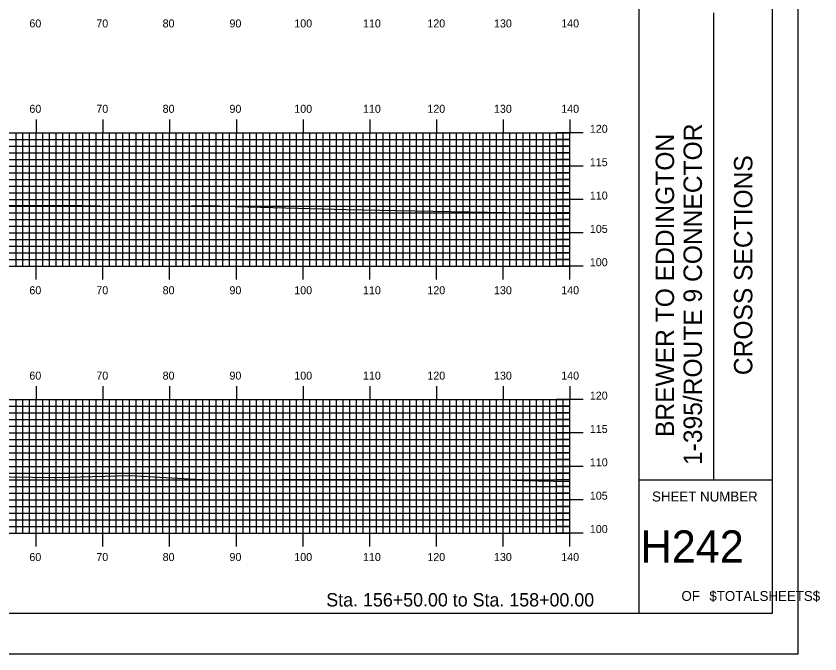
# Model space of a CAD drawing. Extents: x 1779499 to 1779842, y 442591 to 442811.
# Drawn here: x 1779721.8 to 1779842.3, y 442590.5 to 442686.2 of the extents above; entities that cross this region are included whole.
import ezdxf

# ---------------------------------------------------------------- set-up
doc = ezdxf.new("R2010")
doc.units = 0
for name, color, linetype in [('BORDER', 7, 'Continuous'), ('H_V ANNOTATION', 7, 'Continuous'), ('MAJOR', 7, 'Continuous'), ('MINOR', 7, 'Continuous'), ('PLOT BOUNDARY', 7, 'Continuous'), ('S_Roadway_Centerline', 7, 'Continuous')]:
    doc.layers.add(name, color=color, linetype=linetype)

msp = doc.modelspace()

# ---------------------------------------------------------------- linework, layer by layer
at = {"layer": 'BORDER'}
for p, q in [((1779815.24, 442596.67), (1779815.24, 442806.67)), ((1779826.42, 442616.67), (1779826.42, 442686.67)), ((1779815.24, 442616.67), (1779835.24, 442616.67))]:
    msp.add_line(p, q, dxfattribs=at)
msp.add_lwpolyline([(1779515.24, 442596.67), (1779835.24, 442596.67), (1779835.24, 442806.67), (1779515.24, 442806.67)], close=True, dxfattribs=at)
at = {"layer": 'MAJOR'}
for p, q in [((1779724.84, 442670.67), (1779724.84, 442668.67)), ((1779734.84, 442670.67), (1779734.84, 442668.67)), ((1779744.84, 442670.67), (1779744.84, 442668.67)), ((1779754.84, 442670.67), (1779754.84, 442668.67)), ((1779764.84, 442670.67), (1779764.84, 442668.67)), ((1779774.84, 442670.67), (1779774.84, 442668.67)), ((1779784.84, 442670.67), (1779784.84, 442668.67)), ((1779794.84, 442670.67), (1779794.84, 442668.67)), ((1779804.84, 442670.67), (1779804.84, 442668.67)), ((1779524.84, 442668.67), (1779804.84, 442668.67)), ((1779524.84, 442668.67), (1779804.84, 442668.67)), ((1779724.84, 442648.67), (1779724.84, 442668.67)), ((1779734.84, 442648.67), (1779734.84, 442668.67)), ((1779744.84, 442648.67), (1779744.84, 442668.67)), ((1779754.84, 442648.67), (1779754.84, 442668.67)), ((1779764.84, 442648.67), (1779764.84, 442668.67)), ((1779774.84, 442648.67), (1779774.84, 442668.67)), ((1779784.84, 442648.67), (1779784.84, 442668.67)), ((1779794.84, 442648.67), (1779794.84, 442668.67)), ((1779806.85, 442668.67), (1779802.84, 442668.67)), ((1779804.84, 442648.67), (1779804.84, 442668.67)), ((1779804.84, 442648.67), (1779804.84, 442668.67)), ((1779524.84, 442663.67), (1779804.84, 442663.67)), ((1779806.85, 442663.67), (1779802.84, 442663.67)), ((1779524.84, 442658.67), (1779804.84, 442658.67)), ((1779806.85, 442658.67), (1779802.84, 442658.67)), ((1779524.84, 442653.67), (1779804.84, 442653.67)), ((1779806.85, 442653.67), (1779802.84, 442653.67)), ((1779524.84, 442648.67), (1779804.84, 442648.67)), ((1779524.84, 442648.67), (1779804.84, 442648.67)), ((1779724.84, 442646.66), (1779724.84, 442648.67)), ((1779734.84, 442646.66), (1779734.84, 442648.67)), ((1779744.84, 442646.66), (1779744.84, 442648.67)), ((1779754.84, 442646.66), (1779754.84, 442648.67)), ((1779764.84, 442646.66), (1779764.84, 442648.67)), ((1779774.84, 442646.66), (1779774.84, 442648.67)), ((1779784.84, 442646.66), (1779784.84, 442648.67)), ((1779794.84, 442646.66), (1779794.84, 442648.67)), ((1779806.85, 442648.67), (1779802.84, 442648.67)), ((1779804.84, 442646.66), (1779804.84, 442648.67)), ((1779724.84, 442630.67), (1779724.84, 442628.67)), ((1779734.84, 442630.67), (1779734.84, 442628.67)), ((1779744.84, 442630.67), (1779744.84, 442628.67)), ((1779754.84, 442630.67), (1779754.84, 442628.67)), ((1779764.84, 442630.67), (1779764.84, 442628.67)), ((1779774.84, 442630.67), (1779774.84, 442628.67)), ((1779784.84, 442630.67), (1779784.84, 442628.67)), ((1779794.84, 442630.67), (1779794.84, 442628.67)), ((1779804.84, 442630.67), (1779804.84, 442628.67)), ((1779524.84, 442628.67), (1779804.84, 442628.67)), ((1779524.84, 442628.67), (1779804.84, 442628.67)), ((1779724.84, 442608.67), (1779724.84, 442628.67)), ((1779734.84, 442608.67), (1779734.84, 442628.67)), ((1779744.84, 442608.67), (1779744.84, 442628.67)), ((1779754.84, 442608.67), (1779754.84, 442628.67)), ((1779764.84, 442608.67), (1779764.84, 442628.67)), ((1779774.84, 442608.67), (1779774.84, 442628.67)), ((1779784.84, 442608.67), (1779784.84, 442628.67)), ((1779794.84, 442608.67), (1779794.84, 442628.67)), ((1779806.85, 442628.67), (1779802.84, 442628.67)), ((1779804.84, 442608.67), (1779804.84, 442628.67)), ((1779804.84, 442608.67), (1779804.84, 442628.67)), ((1779524.84, 442623.67), (1779804.84, 442623.67)), ((1779806.85, 442623.67), (1779802.84, 442623.67)), ((1779524.84, 442618.67), (1779804.84, 442618.67)), ((1779806.85, 442618.67), (1779802.84, 442618.67)), ((1779524.84, 442613.67), (1779804.84, 442613.67)), ((1779806.85, 442613.67), (1779802.84, 442613.67)), ((1779524.84, 442608.67), (1779804.84, 442608.67)), ((1779524.84, 442608.67), (1779804.84, 442608.67)), ((1779724.84, 442606.66), (1779724.84, 442608.67)), ((1779734.84, 442606.66), (1779734.84, 442608.67)), ((1779744.84, 442606.66), (1779744.84, 442608.67)), ((1779754.84, 442606.66), (1779754.84, 442608.67)), ((1779764.84, 442606.66), (1779764.84, 442608.67)), ((1779774.84, 442606.66), (1779774.84, 442608.67)), ((1779784.84, 442606.66), (1779784.84, 442608.67)), ((1779794.84, 442606.66), (1779794.84, 442608.67)), ((1779806.85, 442608.67), (1779802.84, 442608.67)), ((1779804.84, 442606.66), (1779804.84, 442608.67))]:
    msp.add_line(p, q, dxfattribs=at)
at = {"layer": 'MINOR'}
for p, q in [((1779721.84, 442648.67), (1779721.84, 442668.67)), ((1779722.84, 442648.67), (1779722.84, 442668.67)), ((1779723.84, 442648.67), (1779723.84, 442668.67)), ((1779725.84, 442648.67), (1779725.84, 442668.67)), ((1779726.84, 442648.67), (1779726.84, 442668.67)), ((1779727.84, 442648.67), (1779727.84, 442668.67)), ((1779728.84, 442648.67), (1779728.84, 442668.67)), ((1779729.84, 442648.67), (1779729.84, 442668.67)), ((1779730.84, 442648.67), (1779730.84, 442668.67)), ((1779731.84, 442648.67), (1779731.84, 442668.67)), ((1779732.84, 442648.67), (1779732.84, 442668.67)), ((1779733.84, 442648.67), (1779733.84, 442668.67)), ((1779735.84, 442648.67), (1779735.84, 442668.67)), ((1779736.84, 442648.67), (1779736.84, 442668.67)), ((1779737.84, 442648.67), (1779737.84, 442668.67)), ((1779738.84, 442648.67), (1779738.84, 442668.67)), ((1779739.84, 442648.67), (1779739.84, 442668.67)), ((1779740.84, 442648.67), (1779740.84, 442668.67)), ((1779741.84, 442648.67), (1779741.84, 442668.67)), ((1779742.84, 442648.67), (1779742.84, 442668.67)), ((1779743.84, 442648.67), (1779743.84, 442668.67)), ((1779745.84, 442648.67), (1779745.84, 442668.67)), ((1779746.84, 442648.67), (1779746.84, 442668.67)), ((1779747.84, 442648.67), (1779747.84, 442668.67)), ((1779748.84, 442648.67), (1779748.84, 442668.67)), ((1779749.84, 442648.67), (1779749.84, 442668.67)), ((1779750.84, 442648.67), (1779750.84, 442668.67)), ((1779751.84, 442648.67), (1779751.84, 442668.67)), ((1779752.84, 442648.67), (1779752.84, 442668.67)), ((1779753.84, 442648.67), (1779753.84, 442668.67)), ((1779755.84, 442648.67), (1779755.84, 442668.67)), ((1779756.84, 442648.67), (1779756.84, 442668.67)), ((1779757.84, 442648.67), (1779757.84, 442668.67)), ((1779758.84, 442648.67), (1779758.84, 442668.67)), ((1779759.84, 442648.67), (1779759.84, 442668.67)), ((1779760.84, 442648.67), (1779760.84, 442668.67)), ((1779761.84, 442648.67), (1779761.84, 442668.67)), ((1779762.84, 442648.67), (1779762.84, 442668.67)), ((1779763.84, 442648.67), (1779763.84, 442668.67)), ((1779765.84, 442648.67), (1779765.84, 442668.67)), ((1779766.84, 442648.67), (1779766.84, 442668.67)), ((1779767.84, 442648.67), (1779767.84, 442668.67)), ((1779768.84, 442648.67), (1779768.84, 442668.67)), ((1779769.84, 442648.67), (1779769.84, 442668.67)), ((1779770.84, 442648.67), (1779770.84, 442668.67)), ((1779771.84, 442648.67), (1779771.84, 442668.67)), ((1779772.84, 442648.67), (1779772.84, 442668.67)), ((1779773.84, 442648.67), (1779773.84, 442668.67)), ((1779775.84, 442648.67), (1779775.84, 442668.67)), ((1779776.84, 442648.67), (1779776.84, 442668.67)), ((1779777.84, 442648.67), (1779777.84, 442668.67)), ((1779778.84, 442648.67), (1779778.84, 442668.67)), ((1779779.84, 442648.67), (1779779.84, 442668.67)), ((1779780.84, 442648.67), (1779780.84, 442668.67)), ((1779781.84, 442648.67), (1779781.84, 442668.67)), ((1779782.84, 442648.67), (1779782.84, 442668.67)), ((1779783.84, 442648.67), (1779783.84, 442668.67)), ((1779785.84, 442648.67), (1779785.84, 442668.67)), ((1779786.84, 442648.67), (1779786.84, 442668.67)), ((1779787.84, 442648.67), (1779787.84, 442668.67)), ((1779788.84, 442648.67), (1779788.84, 442668.67)), ((1779789.84, 442648.67), (1779789.84, 442668.67)), ((1779790.84, 442648.67), (1779790.84, 442668.67)), ((1779791.84, 442648.67), (1779791.84, 442668.67)), ((1779792.84, 442648.67), (1779792.84, 442668.67)), ((1779793.84, 442648.67), (1779793.84, 442668.67)), ((1779795.84, 442648.67), (1779795.84, 442668.67)), ((1779796.84, 442648.67), (1779796.84, 442668.67)), ((1779797.84, 442648.67), (1779797.84, 442668.67)), ((1779798.84, 442648.67), (1779798.84, 442668.67)), ((1779799.84, 442648.67), (1779799.84, 442668.67)), ((1779800.84, 442648.67), (1779800.84, 442668.67)), ((1779801.84, 442648.67), (1779801.84, 442668.67)), ((1779802.84, 442648.67), (1779802.84, 442668.67)), ((1779803.84, 442648.67), (1779803.84, 442668.67)), ((1779524.84, 442667.67), (1779804.84, 442667.67)), ((1779804.84, 442667.67), (1779802.84, 442667.67)), ((1779524.84, 442666.67), (1779804.84, 442666.67)), ((1779804.84, 442666.67), (1779802.84, 442666.67)), ((1779524.84, 442665.67), (1779804.84, 442665.67)), ((1779804.84, 442665.67), (1779802.84, 442665.67)), ((1779524.84, 442664.67), (1779804.84, 442664.67)), ((1779804.84, 442664.67), (1779802.84, 442664.67)), ((1779524.84, 442662.67), (1779804.84, 442662.67)), ((1779804.84, 442662.67), (1779802.84, 442662.67)), ((1779524.84, 442661.67), (1779804.84, 442661.67)), ((1779804.84, 442661.67), (1779802.84, 442661.67)), ((1779524.84, 442660.67), (1779804.84, 442660.67)), ((1779804.84, 442660.67), (1779802.84, 442660.67)), ((1779524.84, 442659.67), (1779804.84, 442659.67)), ((1779804.84, 442659.67), (1779802.84, 442659.67)), ((1779524.84, 442657.67), (1779804.84, 442657.67)), ((1779804.84, 442657.67), (1779802.84, 442657.67)), ((1779524.84, 442656.67), (1779804.84, 442656.67)), ((1779804.84, 442656.67), (1779802.84, 442656.67)), ((1779524.84, 442655.67), (1779804.84, 442655.67)), ((1779804.84, 442655.67), (1779802.84, 442655.67)), ((1779524.84, 442654.67), (1779804.84, 442654.67)), ((1779804.84, 442654.67), (1779802.84, 442654.67)), ((1779524.84, 442652.67), (1779804.84, 442652.67)), ((1779524.84, 442651.67), (1779804.84, 442651.67)), ((1779804.84, 442652.67), (1779802.84, 442652.67)), ((1779804.84, 442651.67), (1779802.84, 442651.67)), ((1779524.84, 442650.67), (1779804.84, 442650.67)), ((1779804.84, 442650.67), (1779802.84, 442650.67)), ((1779524.84, 442649.67), (1779804.84, 442649.67)), ((1779804.84, 442649.67), (1779802.84, 442649.67)), ((1779721.84, 442608.67), (1779721.84, 442628.67)), ((1779722.84, 442608.67), (1779722.84, 442628.67)), ((1779723.84, 442608.67), (1779723.84, 442628.67)), ((1779725.84, 442608.67), (1779725.84, 442628.67)), ((1779726.84, 442608.67), (1779726.84, 442628.67)), ((1779727.84, 442608.67), (1779727.84, 442628.67)), ((1779728.84, 442608.67), (1779728.84, 442628.67)), ((1779729.84, 442608.67), (1779729.84, 442628.67)), ((1779730.84, 442608.67), (1779730.84, 442628.67)), ((1779731.84, 442608.67), (1779731.84, 442628.67)), ((1779732.84, 442608.67), (1779732.84, 442628.67)), ((1779733.84, 442608.67), (1779733.84, 442628.67)), ((1779735.84, 442608.67), (1779735.84, 442628.67)), ((1779736.84, 442608.67), (1779736.84, 442628.67)), ((1779737.84, 442608.67), (1779737.84, 442628.67)), ((1779738.84, 442608.67), (1779738.84, 442628.67)), ((1779739.84, 442608.67), (1779739.84, 442628.67)), ((1779740.84, 442608.67), (1779740.84, 442628.67)), ((1779741.84, 442608.67), (1779741.84, 442628.67)), ((1779742.84, 442608.67), (1779742.84, 442628.67)), ((1779743.84, 442608.67), (1779743.84, 442628.67)), ((1779745.84, 442608.67), (1779745.84, 442628.67)), ((1779746.84, 442608.67), (1779746.84, 442628.67)), ((1779747.84, 442608.67), (1779747.84, 442628.67)), ((1779748.84, 442608.67), (1779748.84, 442628.67)), ((1779749.84, 442608.67), (1779749.84, 442628.67)), ((1779750.84, 442608.67), (1779750.84, 442628.67)), ((1779751.84, 442608.67), (1779751.84, 442628.67)), ((1779752.84, 442608.67), (1779752.84, 442628.67)), ((1779753.84, 442608.67), (1779753.84, 442628.67)), ((1779755.84, 442608.67), (1779755.84, 442628.67)), ((1779756.84, 442608.67), (1779756.84, 442628.67)), ((1779757.84, 442608.67), (1779757.84, 442628.67)), ((1779758.84, 442608.67), (1779758.84, 442628.67)), ((1779759.84, 442608.67), (1779759.84, 442628.67)), ((1779760.84, 442608.67), (1779760.84, 442628.67)), ((1779761.84, 442608.67), (1779761.84, 442628.67)), ((1779762.84, 442608.67), (1779762.84, 442628.67)), ((1779763.84, 442608.67), (1779763.84, 442628.67)), ((1779765.84, 442608.67), (1779765.84, 442628.67)), ((1779766.84, 442608.67), (1779766.84, 442628.67)), ((1779767.84, 442608.67), (1779767.84, 442628.67)), ((1779768.84, 442608.67), (1779768.84, 442628.67)), ((1779769.84, 442608.67), (1779769.84, 442628.67)), ((1779770.84, 442608.67), (1779770.84, 442628.67)), ((1779771.84, 442608.67), (1779771.84, 442628.67)), ((1779772.84, 442608.67), (1779772.84, 442628.67)), ((1779773.84, 442608.67), (1779773.84, 442628.67)), ((1779775.84, 442608.67), (1779775.84, 442628.67)), ((1779776.84, 442608.67), (1779776.84, 442628.67)), ((1779777.84, 442608.67), (1779777.84, 442628.67)), ((1779778.84, 442608.67), (1779778.84, 442628.67)), ((1779779.84, 442608.67), (1779779.84, 442628.67)), ((1779780.84, 442608.67), (1779780.84, 442628.67)), ((1779781.84, 442608.67), (1779781.84, 442628.67)), ((1779782.84, 442608.67), (1779782.84, 442628.67)), ((1779783.84, 442608.67), (1779783.84, 442628.67)), ((1779785.84, 442608.67), (1779785.84, 442628.67)), ((1779786.84, 442608.67), (1779786.84, 442628.67)), ((1779787.84, 442608.67), (1779787.84, 442628.67)), ((1779788.84, 442608.67), (1779788.84, 442628.67)), ((1779789.84, 442608.67), (1779789.84, 442628.67)), ((1779790.84, 442608.67), (1779790.84, 442628.67)), ((1779791.84, 442608.67), (1779791.84, 442628.67)), ((1779792.84, 442608.67), (1779792.84, 442628.67)), ((1779793.84, 442608.67), (1779793.84, 442628.67)), ((1779795.84, 442608.67), (1779795.84, 442628.67)), ((1779796.84, 442608.67), (1779796.84, 442628.67)), ((1779797.84, 442608.67), (1779797.84, 442628.67)), ((1779798.84, 442608.67), (1779798.84, 442628.67)), ((1779799.84, 442608.67), (1779799.84, 442628.67)), ((1779800.84, 442608.67), (1779800.84, 442628.67)), ((1779801.84, 442608.67), (1779801.84, 442628.67)), ((1779802.84, 442608.67), (1779802.84, 442628.67)), ((1779803.84, 442608.67), (1779803.84, 442628.67)), ((1779524.84, 442627.67), (1779804.84, 442627.67)), ((1779804.84, 442627.67), (1779802.84, 442627.67)), ((1779524.84, 442626.67), (1779804.84, 442626.67)), ((1779804.84, 442626.67), (1779802.84, 442626.67)), ((1779524.84, 442625.67), (1779804.84, 442625.67)), ((1779804.84, 442625.67), (1779802.84, 442625.67)), ((1779524.84, 442624.67), (1779804.84, 442624.67)), ((1779804.84, 442624.67), (1779802.84, 442624.67)), ((1779524.84, 442622.67), (1779804.84, 442622.67)), ((1779804.84, 442622.67), (1779802.84, 442622.67)), ((1779524.84, 442621.67), (1779804.84, 442621.67)), ((1779804.84, 442621.67), (1779802.84, 442621.67)), ((1779524.84, 442620.67), (1779804.84, 442620.67)), ((1779804.84, 442620.67), (1779802.84, 442620.67)), ((1779524.84, 442619.67), (1779804.84, 442619.67)), ((1779804.84, 442619.67), (1779802.84, 442619.67)), ((1779524.84, 442617.67), (1779804.84, 442617.67)), ((1779524.84, 442616.67), (1779804.84, 442616.67)), ((1779804.84, 442617.67), (1779802.84, 442617.67)), ((1779804.84, 442616.67), (1779802.84, 442616.67)), ((1779524.84, 442615.67), (1779804.84, 442615.67)), ((1779804.84, 442615.67), (1779802.84, 442615.67)), ((1779524.84, 442614.67), (1779804.84, 442614.67)), ((1779804.84, 442614.67), (1779802.84, 442614.67)), ((1779524.84, 442612.67), (1779804.84, 442612.67)), ((1779804.84, 442612.67), (1779802.84, 442612.67)), ((1779524.84, 442611.67), (1779804.84, 442611.67)), ((1779524.84, 442610.67), (1779804.84, 442610.67)), ((1779804.84, 442611.67), (1779802.84, 442611.67)), ((1779804.84, 442610.67), (1779802.84, 442610.67)), ((1779524.84, 442609.67), (1779804.84, 442609.67)), ((1779804.84, 442609.67), (1779802.84, 442609.67))]:
    msp.add_line(p, q, dxfattribs=at)
at = {"layer": 'PLOT BOUNDARY'}
msp.add_lwpolyline([(1779499.06, 442590.55), (1779839.06, 442590.55), (1779839.06, 442810.55), (1779499.06, 442810.55)], close=True, dxfattribs=at)
at = {"layer": 'S_Roadway_Centerline'}
for points in [[(1779707.72, 442657.91), (1779724.69, 442657.78), (1779729.32, 442657.82), (1779739.44, 442657.64), (1779748.1, 442657.72), (1779751.05, 442657.76), (1779754.66, 442657.64), (1779764.11, 442657.36), (1779771.31, 442657.18), (1779778.89, 442657), (1779795.27, 442656.71), (1779798.16, 442656.62), (1779801.63, 442656.64), (1779804.84, 442656.61)], [(1779717.48, 442617.16), (1779727.58, 442616.98), (1779727.73, 442616.98), (1779727.81, 442616.98), (1779738.84, 442617.28), (1779749.74, 442616.7), (1779751.16, 442616.64), (1779761.66, 442616.72), (1779772.68, 442616.73), (1779772.86, 442616.73), (1779773.02, 442616.73), (1779777.13, 442616.71), (1779796.28, 442616.59), (1779797.03, 442616.59), (1779797.7, 442616.57), (1779804.84, 442616.4)]]:
    msp.add_lwpolyline(points, dxfattribs=at)

# ---------------------------------------------------------------- texts
at = {"layer": 'BORDER'}
for s, p in [('1-395/ROUTE 9 CONNECTOR', (1779824.65, 442618.87)), ('BREWER TO EDDINGTON', (1779820.47, 442623.07)), ('CROSS SECTIONS', (1779832.21, 442632.34))]:
    msp.add_text(s, height=2.7557, rotation=90, dxfattribs=at).set_placement(p)
for s, height, p in [('SHEET NUMBER', 1.4905, (1779817.17, 442613.4)), ('H242', 4.839, (1779815.45, 442604.23)), ('OF', 1.491, (1779821.58, 442598.49)), ('$TOTALSHEETS$', 1.4905, (1779825.76, 442598.49))]:
    msp.add_text(s, height=height, dxfattribs=at).set_placement(p)
at = {"layer": 'H_V ANNOTATION'}
for s, height, p in [('60', 1.2, (1779723.81, 442684.47)), ('70', 1.2, (1779733.85, 442684.47)), ('80', 1.2, (1779743.79, 442684.47)), ('90', 1.2, (1779753.81, 442684.47)), ('100', 1.2, (1779763.53, 442684.47)), ('110', 1.2, (1779773.83, 442684.47)), ('120', 1.2, (1779783.48, 442684.47)), ('130', 1.2, (1779793.47, 442684.47)), ('140', 1.2, (1779803.55, 442684.47)), ('60', 1.2, (1779723.81, 442671.67)), ('70', 1.2, (1779733.85, 442671.67)), ('80', 1.2, (1779743.79, 442671.67)), ('90', 1.2, (1779753.81, 442671.67)), ('100', 1.2, (1779763.53, 442671.67)), ('110', 1.2, (1779773.83, 442671.67)), ('120', 1.2, (1779783.48, 442671.67)), ('130', 1.2, (1779793.47, 442671.67)), ('140', 1.2, (1779803.55, 442671.67)), ('120', 1.2, (1779807.84, 442668.67)), ('115', 1.2, (1779807.84, 442663.67)), ('110', 1.2, (1779807.84, 442658.67)), ('105', 1.2, (1779807.84, 442653.67)), ('100', 1.2, (1779807.84, 442648.67)), ('60', 1.2, (1779723.81, 442644.47)), ('70', 1.2, (1779733.85, 442644.47)), ('80', 1.2, (1779743.79, 442644.47)), ('90', 1.2, (1779753.81, 442644.47)), ('100', 1.2, (1779763.53, 442644.47)), ('110', 1.2, (1779773.83, 442644.47)), ('120', 1.2, (1779783.48, 442644.47)), ('130', 1.2, (1779793.47, 442644.47)), ('140', 1.2, (1779803.55, 442644.47)), ('60', 1.2, (1779723.81, 442631.67)), ('70', 1.2, (1779733.85, 442631.67)), ('80', 1.2, (1779743.79, 442631.67)), ('90', 1.2, (1779753.81, 442631.67)), ('100', 1.2, (1779763.53, 442631.67)), ('110', 1.2, (1779773.83, 442631.67)), ('120', 1.2, (1779783.48, 442631.67)), ('130', 1.2, (1779793.47, 442631.67)), ('140', 1.2, (1779803.55, 442631.67)), ('120', 1.2, (1779807.84, 442628.67)), ('115', 1.2, (1779807.84, 442623.67)), ('110', 1.2, (1779807.84, 442618.67)), ('105', 1.2, (1779807.84, 442613.67)), ('100', 1.2, (1779807.84, 442608.67)), ('60', 1.2, (1779723.81, 442604.47)), ('70', 1.2, (1779733.85, 442604.47)), ('80', 1.2, (1779743.79, 442604.47)), ('90', 1.2, (1779753.81, 442604.47)), ('100', 1.2, (1779763.53, 442604.47)), ('110', 1.2, (1779773.83, 442604.47)), ('120', 1.2, (1779783.48, 442604.47)), ('130', 1.2, (1779793.47, 442604.47)), ('140', 1.2, (1779803.55, 442604.47)), ('Sta. 156+50.00 to Sta. 158+00.00', 2.0004, (1779768.33, 442597.66))]:
    msp.add_text(s, height=height, dxfattribs=at).set_placement(p)

doc.saveas('drawing.dxf')
